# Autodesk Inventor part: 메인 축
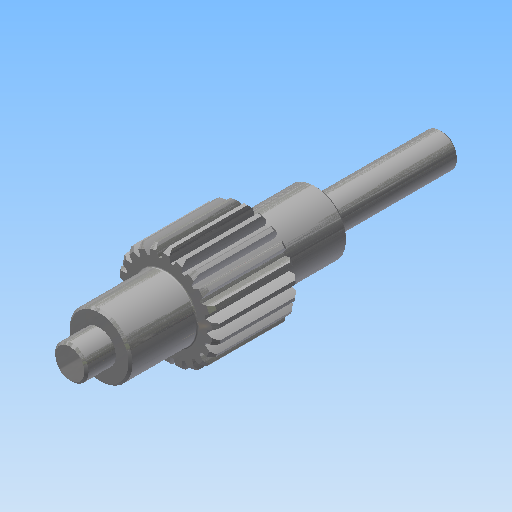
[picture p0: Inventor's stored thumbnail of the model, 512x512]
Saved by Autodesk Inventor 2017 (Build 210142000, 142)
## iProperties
Created: 2016-02
Part Number: 메인 축
Material: 강철, 연강
Document SubType Name: Modeling
Categories: <?xml version="1.0" encoding="UTF-16"?> <MemberInstance><Categories><FamilyTemplate><FamilyTemplateParameter ValueType="xs:double" Id="1" ObjectReferenceKey="da
Density: 7.86 g/cm^3
Appearance: 강철
CustomPartVersion: 1
Author: mdu
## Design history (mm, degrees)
sketch "Sketch1"
  geometry: C1 r 12 at (0, 0)
  constraints: 1 centre point
  dimensions: "d0" = 24 diameter of C1 (= da_da)
extrude "Extrusion1" new body sketch "Sketch1" distance "d1" = 20 (= da_b); taper "d2" = 0 deg
workplane "Work Plane2"
feature "피치 지름" dims "d4" = 10, "d5" = 0
workplane "Work Plane8"
workplane "Work Plane9"
chamfer "모따기1" distance "d49" = 1; stored, may be unused: second distance "d50" = 2, angle "d51" = 45 deg
sketch "스케치3"
  geometry: C1 r 7.5 at (0, 0); 1 further point
  constraints: 1 centre point, 1 coincident
  dimensions: "d52" = 15 diameter of C1
extrude "돌출2" join sketch "스케치3" distance "d53" = 16; taper "d54" = 0 deg
sketch "스케치4"
  geometry: C1 r 4 at (0, 0); 1 further point
  constraints: 1 centre point, 1 coincident
  dimensions: "d55" = 8 diameter of C1
extrude "돌출3" join sketch "스케치4" distance "d56" = 7; taper "d57" = 0 deg
sketch "스케치5"
  geometry: C1 r 7.5 at (0, 0) reference; C2 r 7.5 at (0, 0) reference; 1 further point
extrude "돌출4" join sketch "스케치5" distance "d62" = 16; taper "d63" = 0 deg
sketch "스케치6"
  geometry: C1 r 4 at (0, 0); 1 further point
  constraints: 1 centre point, 1 coincident
  dimensions: "d64" = 8 diameter of C1
extrude "돌출5" join sketch "스케치6" distance "d65" = 30; taper "d66" = 0 deg
chamfer "모따기2" distance "d58" = 0.5; stored, may be unused: second distance "d59" = 2, angle "d60" = 45 deg
fillet "모깎기1" dims "d61" = 0.3
feature "스퍼 기어" dims "da_b" = 20, "da_d" = 22, "da_aw" = 31, "da_da" = 24, "da_df" = 19.5, "da_dw" = 22, angle "da_beta" = 0 deg, "da_lefttooth" = 0, "da_righttooth" = 0
body "Solid1"
sketch "Sketch2"
  geometry: C1 r 12 at (0, 0) reference; C2 r 11 at (0, 0)
  constraints: 1 centre point, 1 coincident
  dimensions: "d3" = 22 diameter of C2 (= da_dw)
body "Srf1"
node "투영된 루프1"
other parameters: "d16" = 31 (= da_aw), "d17" = 0, "d34" = 1.428 (computed from da_z), "d39" = 0, "d41" = 0, "d43" = 31 (= da_aw), "d46" = 31 (= da_aw), "d47" = 0, "d48" = 0
